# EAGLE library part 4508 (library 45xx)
Dual 4-bit LATCH
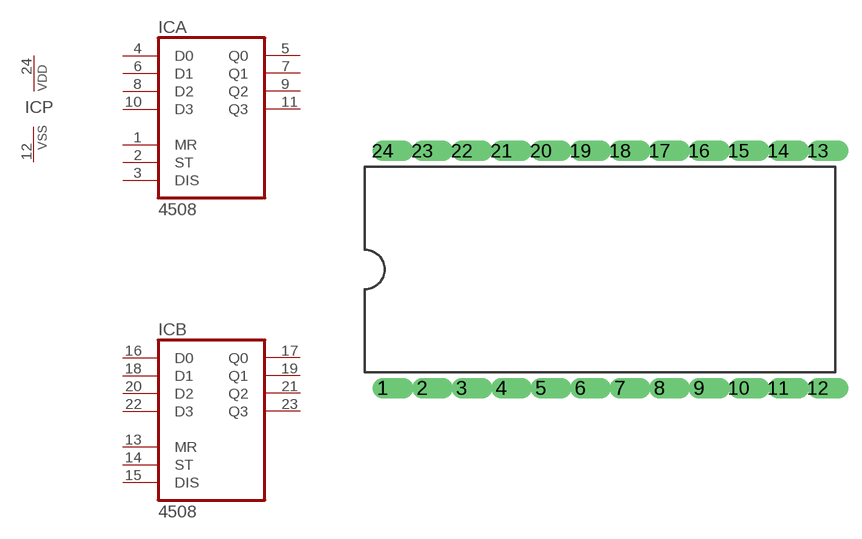
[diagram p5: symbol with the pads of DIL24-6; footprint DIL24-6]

Designator prefix IC; gates A=4508 B=4508 P=PWRN

## 4508N  [DIL24-6]
1  A:MR  in
2  A:ST  in
3  A:DIS  in
4  A:D0  in
5  A:Q0  out
6  A:D1  in
7  A:Q1  out
8  A:D2  in
9  A:Q2  out
10  A:D3  in
11  A:Q3  out
12  P:VSS  pwr
13  B:MR  in
14  B:ST  in
15  B:DIS  in
16  B:D0  in
17  B:Q0  out
18  B:D1  in
19  B:Q1  out
20  B:D2  in
21  B:Q2  out
22  B:D3  in
23  B:Q3  out
24  P:VDD  pwr

## Footprint DIL24-6 (pad centres in mm)
Dual In Line 0.6 inch
drill 0.813 offset: 1 -13.97,-7.62; 2 -11.43,-7.62; 3 -8.89,-7.62; 4 -6.35,-7.62; 5 -3.81,-7.62; 6 -1.27,-7.62; 7 1.27,-7.62; 8 3.81,-7.62; 9 6.35,-7.62; 10 8.89,-7.62; 11 11.43,-7.62; 12 13.97,-7.62; 13 13.97,7.62; 14 11.43,7.62; 15 8.89,7.62; 16 6.35,7.62; 17 3.81,7.62; 18 1.27,7.62; 19 -1.27,7.62; 20 -3.81,7.62; 21 -6.35,7.62; 22 -8.89,7.62; 23 -11.43,7.62; 24 -13.97,7.62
